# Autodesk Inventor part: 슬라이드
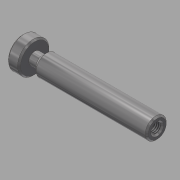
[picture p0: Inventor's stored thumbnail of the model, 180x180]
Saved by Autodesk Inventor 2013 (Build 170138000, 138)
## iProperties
Created: 2015-12
Part Number: 슬라이드
Document SubType Name: Modeling
Designer: mdu
Density: 8.08 g/cm^3
Material: 스테인리스강
Mass: 114.493 g
Surface Area: 49.8963 cm^2
Volume: 14.17 cm^3
Author: mdu
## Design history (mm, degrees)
sketch "스케치1"
  geometry: L1 (-45, 0)-(45, 0); L2 (-45, 0)-(-45, 10.5); L3 (-45, 10.5)-(-37, 10.5); L4 (-37, 10.5)-(-37, 4); L5 (-37, 4)-(-32, 4); L6 (-32, 4)-(-29, 7); L7 (-29, 7)-(45, 7); L8 (45, 7)-(45, 0); 2 further points
  constraints: 16 end point, 4 parallel, 2 perpendicular, 1 coincident, 1 horizontal, 1 midpoint
  dimensions: "d0" = 90 distance of L1.start L1.end; "d1" = 21 diameter of L3 L1; "d2" = 14 diameter of L7 L1; "d3" = 8 diameter of L5 L1; "d4" = 8 distance of L2.end L3.end; "d5" = 5 distance of L4.end L5.end; "d6" = 135 deg angle of L6 L5
revolve "회전1" sketch "스케치1" stored, may be unused: angle "d7" = 90 deg
chamfer "모따기1" distance "d8" = 1; stored, may be unused: second distance "d9" = 2, angle "d10" = 45 deg
hole "구멍1" diameter "d13" = 6.647; stored, may be unused: countersink angle "d17" = 90 deg, drill point angle "d19" = 118 deg; dims "d11" = 10, "d12" = 10, "d14" = 9, "d15" = 4, "d16" = 2, "d18" = 12
chamfer "모따기2" distance "d20" = 1; stored, may be unused: second distance "d21" = 2, angle "d22" = 45 deg
node "솔리드1"
